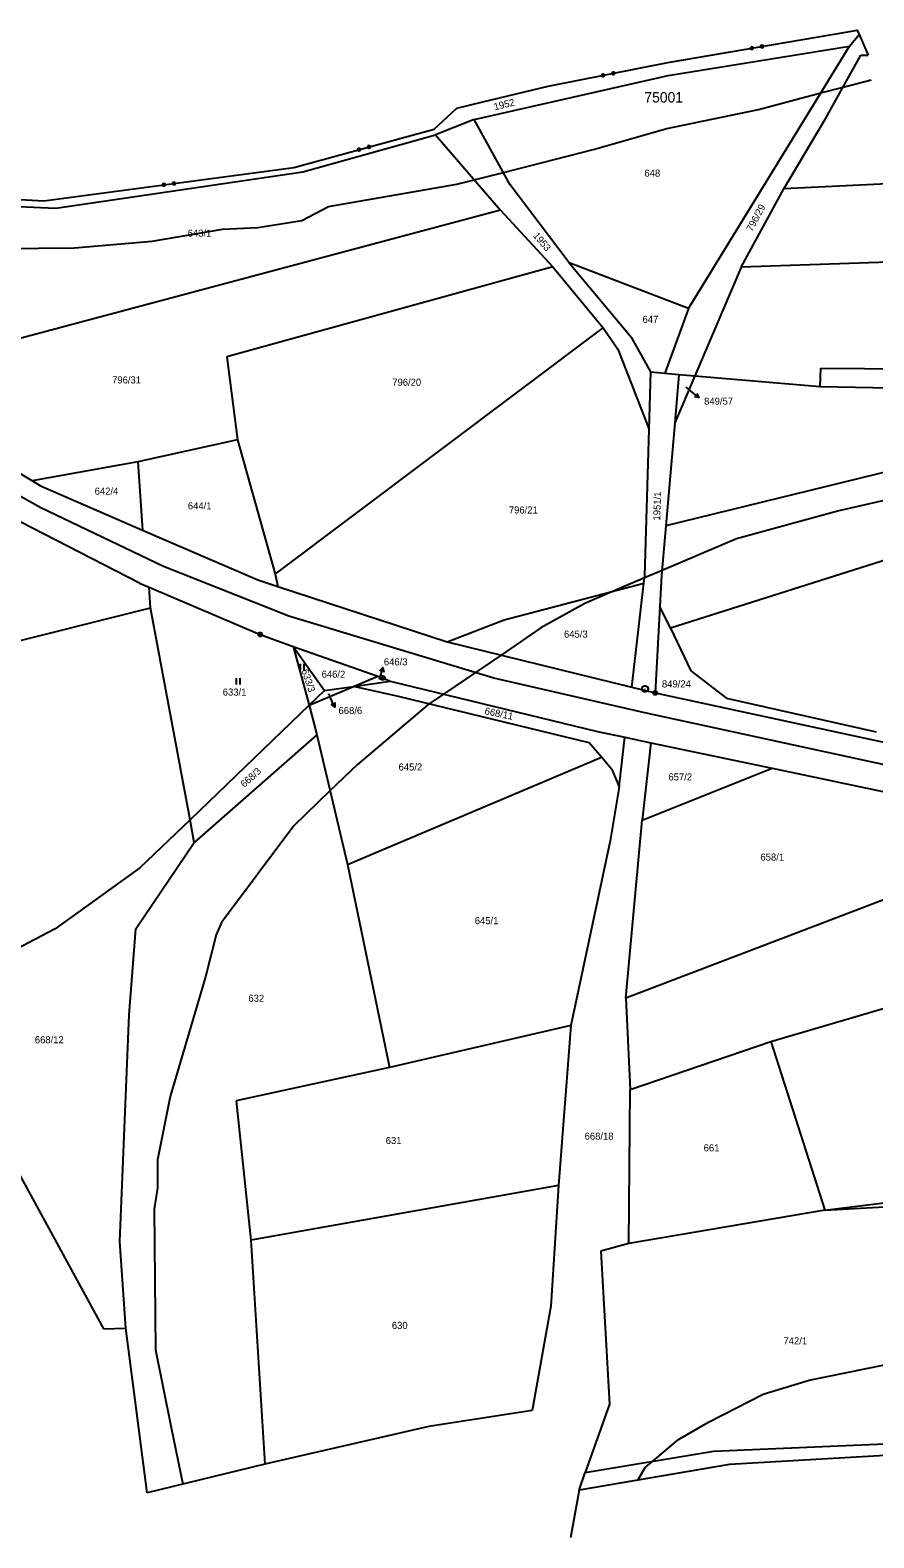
# Model space of a CAD drawing. Extents: x -789470 to -786707, y -1118640 to -1114455.
# Drawn here: x -789211.5 to -789008.6, y -1114817.3 to -1114454.9 of the extents above; entities that cross this region are included whole.
import ezdxf

# ---------------------------------------------------------------- set-up
doc = ezdxf.new("R2010")
doc.units = 0
for name, color, linetype in [('1', 7, 'Continuous'), ('11', 7, 'Continuous'), ('2', 7, 'Continuous'), ('3', 7, 'Continuous'), ('6', 7, 'Continuous'), ('7', 7, 'Continuous'), ('8', 7, 'Continuous')]:
    doc.layers.add(name, color=color, linetype=linetype)

msp = doc.modelspace()

# ---------------------------------------------------------------- linework, layer by layer
at = {"layer": '1'}
for p, q in [((-789058.11, -1114462.67), (-789015.34, -1114455.34)), ((-789015.34, -1114455.34), (-789012.6, -1114454.87)), ((-789014.4, -1114458.72), (-789012.14, -1114455.9)), ((-789012.6, -1114454.87), (-789012.14, -1114455.9)), ((-789012.14, -1114455.9), (-789009.91, -1114460.91)), ((-789058.02, -1114465.78), (-789014.4, -1114458.72)), ((-789053.12, -1114521.81), (-789014.4, -1114458.72)), ((-789020.14, -1114476.06), (-789011.74, -1114460.92)), ((-789011.74, -1114460.92), (-789009.91, -1114460.91)), ((-789086.93, -1114468.3), (-789058.11, -1114462.67)), ((-789104.7, -1114476.36), (-789058.02, -1114465.78)), ((-789102.63, -1114472.12), (-789086.93, -1114468.3)), ((-789108.83, -1114473.62), (-789102.63, -1114472.12)), ((-789114.34, -1114478.64), (-789108.83, -1114473.62)), ((-789030.25, -1114493.04), (-789020.14, -1114476.06)), ((-789148.09, -1114487.9), (-789114.34, -1114478.64)), ((-789104.7, -1114476.36), (-789114.01, -1114480.01)), ((-789096.01, -1114492.03), (-789104.7, -1114476.36)), ((-789145.89, -1114488.93), (-789114.01, -1114480.01)), ((-789114.01, -1114480.01), (-789098.37, -1114498.11)), ((-789208.22, -1114495.86), (-789148.09, -1114487.9)), ((-789205.27, -1114497.63), (-789145.89, -1114488.93)), ((-789081.84, -1114510.76), (-789096.01, -1114492.03)), ((-789040.51, -1114511.82), (-789030.25, -1114493.04)), ((-788982.26, -1114490.73), (-789030.25, -1114493.04)), ((-789235.33, -1114496.28), (-789205.27, -1114497.63)), ((-789233.65, -1114494.43), (-789208.22, -1114495.86)), ((-789098.37, -1114498.11), (-789235.7, -1114534.82)), ((-789098.37, -1114498.11), (-789085.8, -1114511.75)), ((-789085.8, -1114511.75), (-789164.15, -1114533.39)), ((-789085.8, -1114511.75), (-789073.65, -1114526.45)), ((-789081.84, -1114510.76), (-789066.76, -1114528.8)), ((-789053.12, -1114521.81), (-789081.84, -1114510.76)), ((-789040.51, -1114511.82), (-789051.65, -1114537.98)), ((-788977.92, -1114509.77), (-789040.51, -1114511.82)), ((-789053.12, -1114521.81), (-789058.81, -1114537.34)), ((-789152.59, -1114585.65), (-789073.65, -1114526.45)), ((-789073.65, -1114526.45), (-789070.17, -1114531.53)), ((-789062.23, -1114537.02), (-789066.76, -1114528.8)), ((-789164.15, -1114533.39), (-789161.58, -1114553.31)), ((-789070.17, -1114531.53), (-789062.63, -1114550.87)), ((-789062.63, -1114550.87), (-789062.23, -1114537.02)), ((-789062.23, -1114537.02), (-789058.81, -1114537.34)), ((-789058.81, -1114537.34), (-789055.45, -1114537.66)), ((-789055.45, -1114537.66), (-789056.45, -1114549.25)), ((-789055.45, -1114537.66), (-789051.65, -1114537.98)), ((-789021.49, -1114540.49), (-789021.34, -1114536.08)), ((-789021.34, -1114536.08), (-788942, -1114536.9)), ((-789051.65, -1114537.98), (-789056.45, -1114549.25)), ((-789051.65, -1114537.98), (-789021.49, -1114540.49)), ((-789021.49, -1114540.49), (-788941.63, -1114542.1)), ((-789211.01, -1114563.21), (-789234.48, -1114549.02)), ((-789063.65, -1114585.99), (-789062.63, -1114550.87)), ((-789056.45, -1114549.25), (-789058.59, -1114574)), ((-789161.58, -1114553.31), (-789185.62, -1114558.65)), ((-789161.58, -1114553.31), (-789152.59, -1114585.65)), ((-788973.71, -1114553.25), (-789058.59, -1114574)), ((-789185.62, -1114558.65), (-789211.01, -1114563.21)), ((-789185.62, -1114558.65), (-789184.43, -1114575.03)), ((-789185.19, -1114587.78), (-789226.93, -1114566.34)), ((-789209.16, -1114564.33), (-789211.01, -1114563.21)), ((-789209.16, -1114564.33), (-789184.43, -1114575.03)), ((-788978.27, -1114573.47), (-789057.48, -1114598.57)), ((-789184.43, -1114575.03), (-789156.73, -1114587.01)), ((-789058.59, -1114574), (-789059.61, -1114585.85)), ((-789185.19, -1114587.78), (-789182.88, -1114588.76)), ((-789156.73, -1114587.01), (-789151.91, -1114588.58)), ((-789152.59, -1114585.65), (-789151.91, -1114588.58)), ((-789097.51, -1114596.62), (-789063.86, -1114587.76)), ((-789066.78, -1114612.81), (-789063.86, -1114587.76)), ((-789063.86, -1114587.76), (-789063.65, -1114585.99)), ((-789059.61, -1114585.85), (-789060.02, -1114593.38)), ((-789182.53, -1114593.72), (-789182.88, -1114588.76)), ((-789182.88, -1114588.76), (-789156.19, -1114600.12)), ((-789151.91, -1114588.58), (-789111.21, -1114601.86)), ((-789254.23, -1114611.62), (-789182.53, -1114593.72)), ((-789173.03, -1114644.64), (-789182.53, -1114593.72)), ((-789060.02, -1114593.38), (-789061.16, -1114614.19)), ((-789057.48, -1114598.57), (-789060.02, -1114593.38)), ((-789111.21, -1114601.86), (-789097.51, -1114596.62)), ((-789057.48, -1114598.57), (-789052.56, -1114608.9)), ((-789156.19, -1114600.12), (-789148.2, -1114602.99)), ((-789111.21, -1114601.86), (-789066.78, -1114612.81)), ((-789148.2, -1114602.99), (-789140.73, -1114613.63)), ((-789148.2, -1114602.99), (-789144.37, -1114617.13)), ((-789148.2, -1114602.99), (-789127.89, -1114610.16)), ((-789133.75, -1114612.63), (-789127.89, -1114610.16)), ((-789127.89, -1114610.16), (-789126.69, -1114610.58)), ((-789052.56, -1114608.9), (-789043.9, -1114615.51)), ((-789144.37, -1114617.13), (-789133.75, -1114612.63)), ((-789140.73, -1114613.63), (-789144.37, -1114617.13)), ((-789140.73, -1114613.63), (-789133.75, -1114612.63)), ((-789133.75, -1114612.63), (-789124.89, -1114611.37)), ((-789122.87, -1114615.05), (-789133.75, -1114612.63)), ((-789126.69, -1114610.58), (-789124.89, -1114611.37)), ((-789124.89, -1114611.37), (-789075.07, -1114623.43)), ((-789066.78, -1114612.81), (-789061.16, -1114614.19)), ((-789144.37, -1114617.13), (-789173.03, -1114644.64)), ((-789144.37, -1114617.13), (-789142.56, -1114624.27)), ((-789077.02, -1114626.15), (-789122.87, -1114615.05)), ((-789061.16, -1114614.19), (-789002.52, -1114626.82)), ((-789007.92, -1114623.62), (-789043.9, -1114615.51)), ((-789142.56, -1114624.27), (-789172.01, -1114650.12)), ((-789142.56, -1114624.27), (-789135.19, -1114655.38)), ((-789075.07, -1114623.43), (-789068.5, -1114624.81)), ((-789074.08, -1114629.62), (-789077.02, -1114626.15)), ((-789069.8, -1114636.75), (-789068.5, -1114624.81)), ((-789068.5, -1114624.81), (-789062.17, -1114626.14)), ((-789062.17, -1114626.14), (-789064.29, -1114644.75)), ((-789062.17, -1114626.14), (-789033.04, -1114632.27)), ((-789135.19, -1114655.38), (-789074.08, -1114629.62)), ((-789071.61, -1114632.54), (-789074.08, -1114629.62)), ((-789071.61, -1114632.54), (-789069.8, -1114636.75)), ((-789064.29, -1114644.75), (-789033.04, -1114632.27)), ((-789033.04, -1114632.27), (-788962.34, -1114647.14)), ((-789069.8, -1114636.75), (-789072.01, -1114649.72)), ((-789173.03, -1114644.64), (-789185.07, -1114656.2)), ((-789172.01, -1114650.12), (-789173.03, -1114644.64)), ((-789068.19, -1114687.52), (-789064.29, -1114644.75)), ((-789072.01, -1114649.72), (-789081.42, -1114694.09)), ((-788962.34, -1114647.14), (-789068.19, -1114687.52)), ((-789186.06, -1114670.85), (-789172.01, -1114650.12)), ((-789185.07, -1114656.2), (-789205.44, -1114670.9)), ((-789135.19, -1114655.38), (-789125.09, -1114704.18)), ((-789205.44, -1114670.9), (-789224.81, -1114680.95)), ((-789187.7, -1114691.53), (-789186.06, -1114670.85)), ((-789033.32, -1114697.94), (-788966.91, -1114678.44)), ((-789068.19, -1114687.52), (-789067.21, -1114709.5)), ((-789189.88, -1114746), (-789187.7, -1114691.53)), ((-789081.42, -1114694.09), (-789125.09, -1114704.18)), ((-789081.42, -1114694.09), (-789084.4, -1114732.6)), ((-789067.21, -1114709.5), (-789033.32, -1114697.94)), ((-789033.32, -1114697.94), (-789020.4, -1114738.52)), ((-789229.14, -1114702.4), (-789193.8, -1114767.06)), ((-789125.09, -1114704.18), (-789161.91, -1114712.24)), ((-789067.47, -1114746.51), (-789067.21, -1114709.5)), ((-789161.91, -1114712.24), (-789158.44, -1114745.74)), ((-789084.4, -1114732.6), (-789158.44, -1114745.74)), ((-789084.4, -1114732.6), (-789086.25, -1114761.61)), ((-789020.4, -1114738.52), (-788983.29, -1114733.88)), ((-789020.4, -1114738.52), (-788982.99, -1114736.42)), ((-789020.4, -1114738.52), (-789067.47, -1114746.51)), ((-789188.44, -1114766.9), (-789189.88, -1114746)), ((-789158.44, -1114745.74), (-789155.02, -1114799.55)), ((-789067.47, -1114746.51), (-789074.21, -1114748.39)), ((-789074.21, -1114748.39), (-789072.14, -1114785.12)), ((-789086.25, -1114761.61), (-789090.77, -1114786.68)), ((-789193.8, -1114767.06), (-789188.44, -1114766.9)), ((-789183.37, -1114806.46), (-789188.44, -1114766.9)), ((-789090.77, -1114786.68), (-789115.62, -1114790.46)), ((-789072.14, -1114785.12), (-789078.02, -1114801.56)), ((-789115.62, -1114790.46), (-789155.02, -1114799.55)), ((-789047.11, -1114796.42), (-788981.24, -1114793.65)), ((-789078.02, -1114801.56), (-789047.11, -1114796.42)), ((-788986.34, -1114796.35), (-789043.29, -1114799.67)), ((-789155.02, -1114799.55), (-789183.37, -1114806.46)), ((-789043.29, -1114799.67), (-789079.41, -1114805.81)), ((-789079.41, -1114805.81), (-789078.02, -1114801.56)), ((-789079.41, -1114805.81), (-789081.5, -1114817.26))]:
    msp.add_line(p, q, dxfattribs=at)
for points in [[(-789037.83, -1114458.87), (-789037.61, -1114459.03), (-789037.57, -1114459.29), (-789037.72, -1114459.51), (-789037.99, -1114459.56), (-789038.21, -1114459.4), (-789038.25, -1114459.14), (-789038.1, -1114458.92), (-789037.83, -1114458.87), (-789037.84, -1114458.91), (-789038.07, -1114458.95), (-789038.14, -1114459.04), (-789037.74, -1114458.98), (-789037.65, -1114459.04), (-789038.2, -1114459.14), (-789038.19, -1114459.22), (-789037.64, -1114459.12), (-789037.62, -1114459.2), (-789038.18, -1114459.29), (-789038.16, -1114459.37), (-789037.61, -1114459.28), (-789037.68, -1114459.37), (-789038.07, -1114459.44), (-789037.98, -1114459.5), (-789037.74, -1114459.46)], [(-789035.37, -1114458.45), (-789035.15, -1114458.6), (-789035.1, -1114458.87), (-789035.26, -1114459.09), (-789035.53, -1114459.13), (-789035.75, -1114458.98), (-789035.79, -1114458.71), (-789035.64, -1114458.49), (-789035.37, -1114458.45), (-789035.39, -1114458.49), (-789035.63, -1114458.53), (-789035.69, -1114458.63), (-789035.3, -1114458.56), (-789035.21, -1114458.62), (-789035.76, -1114458.72), (-789035.75, -1114458.8), (-789035.19, -1114458.7), (-789035.18, -1114458.78), (-789035.73, -1114458.88), (-789035.72, -1114458.95), (-789035.17, -1114458.86), (-789035.23, -1114458.95), (-789035.63, -1114459.02), (-789035.53, -1114459.08), (-789035.3, -1114459.04)], [(-789071.18, -1114464.9), (-789070.96, -1114465.05), (-789070.9, -1114465.31), (-789071.05, -1114465.53), (-789071.32, -1114465.59), (-789071.54, -1114465.44), (-789071.59, -1114465.17), (-789071.44, -1114464.95), (-789071.18, -1114464.9), (-789071.2, -1114464.94), (-789071.44, -1114464.99), (-789071.5, -1114465.08), (-789071.11, -1114465), (-789071.01, -1114465.07), (-789071.56, -1114465.18), (-789071.55, -1114465.25), (-789071, -1114465.15), (-789070.98, -1114465.23), (-789071.53, -1114465.33), (-789071.52, -1114465.41), (-789070.97, -1114465.3), (-789071.03, -1114465.4), (-789071.42, -1114465.47), (-789071.33, -1114465.54), (-789071.09, -1114465.49)], [(-789073.63, -1114465.38), (-789073.41, -1114465.53), (-789073.36, -1114465.79), (-789073.51, -1114466.01), (-789073.77, -1114466.07), (-789073.99, -1114465.92), (-789074.05, -1114465.65), (-789073.9, -1114465.43), (-789073.63, -1114465.38), (-789073.63, -1114465.42), (-789073.87, -1114465.46), (-789073.93, -1114465.56), (-789073.54, -1114465.48), (-789073.45, -1114465.54), (-789074, -1114465.65), (-789073.98, -1114465.73), (-789073.43, -1114465.62), (-789073.42, -1114465.7), (-789073.96, -1114465.81), (-789073.95, -1114465.89), (-789073.4, -1114465.78), (-789073.46, -1114465.87), (-789073.86, -1114465.95), (-789073.76, -1114466.01), (-789073.53, -1114465.97)], [(-789132.33, -1114483.24), (-789132.1, -1114483.38), (-789132.03, -1114483.64), (-789132.16, -1114483.87), (-789132.42, -1114483.94), (-789132.65, -1114483.81), (-789132.72, -1114483.55), (-789132.59, -1114483.32), (-789132.33, -1114483.24), (-789132.33, -1114483.29), (-789132.56, -1114483.35), (-789132.62, -1114483.45), (-789132.23, -1114483.34), (-789132.13, -1114483.4), (-789132.67, -1114483.55), (-789132.65, -1114483.62), (-789132.11, -1114483.48), (-789132.09, -1114483.55), (-789132.63, -1114483.7), (-789132.61, -1114483.78), (-789132.07, -1114483.63), (-789132.13, -1114483.73), (-789132.51, -1114483.83), (-789132.41, -1114483.89), (-789132.18, -1114483.83)], [(-789129.92, -1114482.58), (-789129.69, -1114482.72), (-789129.62, -1114482.98), (-789129.75, -1114483.21), (-789130.01, -1114483.28), (-789130.24, -1114483.15), (-789130.31, -1114482.89), (-789130.18, -1114482.65), (-789129.92, -1114482.58), (-789129.94, -1114482.63), (-789130.17, -1114482.69), (-789130.23, -1114482.79), (-789129.84, -1114482.69), (-789129.74, -1114482.74), (-789130.28, -1114482.89), (-789130.26, -1114482.97), (-789129.72, -1114482.82), (-789129.7, -1114482.9), (-789130.24, -1114483.04), (-789130.22, -1114483.12), (-789129.68, -1114482.97), (-789129.73, -1114483.07), (-789130.12, -1114483.18), (-789130.02, -1114483.23), (-789129.79, -1114483.17)], [(-789179.26, -1114491.7), (-789179.04, -1114491.87), (-789179.01, -1114492.13), (-789179.17, -1114492.35), (-789179.44, -1114492.38), (-789179.65, -1114492.22), (-789179.69, -1114491.95), (-789179.53, -1114491.74), (-789179.26, -1114491.7), (-789179.26, -1114491.74), (-789179.5, -1114491.78), (-789179.57, -1114491.87), (-789179.17, -1114491.81), (-789179.08, -1114491.88), (-789179.64, -1114491.96), (-789179.63, -1114492.04), (-789179.07, -1114491.96), (-789179.06, -1114492.04), (-789179.62, -1114492.11), (-789179.61, -1114492.19), (-789179.05, -1114492.12), (-789179.12, -1114492.21), (-789179.52, -1114492.26), (-789179.43, -1114492.33), (-789179.19, -1114492.3)], [(-789176.78, -1114491.37), (-789176.57, -1114491.54), (-789176.53, -1114491.81), (-789176.69, -1114492.02), (-789176.96, -1114492.05), (-789177.18, -1114491.89), (-789177.21, -1114491.62), (-789177.05, -1114491.41), (-789176.78, -1114491.37), (-789176.8, -1114491.42), (-789177.04, -1114491.45), (-789177.11, -1114491.54), (-789176.71, -1114491.49), (-789176.62, -1114491.56), (-789177.18, -1114491.63), (-789177.17, -1114491.71), (-789176.61, -1114491.64), (-789176.6, -1114491.71), (-789177.16, -1114491.79), (-789177.15, -1114491.87), (-789176.59, -1114491.79), (-789176.66, -1114491.88), (-789177.06, -1114491.94), (-789176.97, -1114492), (-789176.73, -1114491.97)]]:
    msp.add_lwpolyline(points, dxfattribs=at)
at = {"layer": '11'}
for points in [[(-789309.5, -1114485.53), (-789305.22, -1114485.95), (-789297.1, -1114486.75), (-789298.04, -1114487.53), (-789284.18, -1114488.99), (-789233.65, -1114494.43), (-789208.22, -1114495.86), (-789148.09, -1114487.9), (-789114.34, -1114478.64), (-789108.83, -1114473.62), (-789102.63, -1114472.12), (-789086.93, -1114468.3), (-789058.11, -1114462.67), (-789015.34, -1114455.34), (-789012.6, -1114454.87), (-789012.14, -1114455.9), (-789009.91, -1114460.91)], [(-789306.68, -1114493.77), (-789304.24, -1114494.87), (-789293.55, -1114499.73), (-789275.34, -1114502.75), (-789238.07, -1114507.53), (-789235.44, -1114507.5), (-789200.79, -1114507.22), (-789182.14, -1114505.59), (-789165.19, -1114502.68), (-789156.72, -1114502.29), (-789146.12, -1114500.63), (-789139.76, -1114497.27), (-789108.83, -1114491.87), (-789104.67, -1114490.82), (-789097.67, -1114489.05), (-789075.77, -1114483.51), (-789058.39, -1114478.49), (-789036.35, -1114473.91), (-789021.31, -1114469.97), (-789015.99, -1114468.58), (-789009.22, -1114466.81)], [(-788986.09, -1114563.33), (-789017.03, -1114570.42), (-789041.61, -1114577.11), (-789059.51, -1114584.74), (-789063.71, -1114586.53), (-789071.06, -1114589.66), (-789078.07, -1114592.64), (-789088.67, -1114598.53), (-789098.24, -1114605.06), (-789112.05, -1114614.48), (-789115.5, -1114616.83), (-789115.82, -1114617.06), (-789132.79, -1114631.38), (-789139.37, -1114637.74), (-789148.06, -1114646.14), (-789165.47, -1114669.35), (-789166.75, -1114672.31), (-789169.31, -1114682.45), (-789177.83, -1114711.19), (-789180.82, -1114726.41), (-789180.83, -1114733.17), (-789181.69, -1114738.25), (-789181.32, -1114772.09), (-789177.54, -1114790.71), (-789174.77, -1114804.36), (-789174.77, -1114804.36)], [(-789065.35, -1114803.42), (-789063.59, -1114800.39), (-789061.76, -1114798.86), (-789055.53, -1114793.64), (-789048.32, -1114789.44), (-789035.18, -1114782.71), (-789024.16, -1114779.36), (-789001.7, -1114774.78)]]:
    msp.add_lwpolyline(points, dxfattribs=at)
at = {"layer": '3'}
for p, q in [((-789146.58, -1114607.18), (-789146.58, -1114608.68)), ((-789145.58, -1114608.68), (-789145.58, -1114607.18)), ((-789161.95, -1114610.64), (-789161.95, -1114612.14)), ((-789160.95, -1114612.14), (-789160.95, -1114610.64))]:
    msp.add_line(p, q, dxfattribs=at)
at = {"layer": '6'}
for p, q in [((-789208.89, -1114569.65), (-789234.69, -1114555.47)), ((-789179.37, -1114583.82), (-789208.89, -1114569.65)), ((-789149.25, -1114595.76), (-789179.37, -1114583.82)), ((-789099.94, -1114610.66), (-789149.25, -1114595.76)), ((-789063.67, -1114618.94), (-789099.94, -1114610.66)), ((-789004.18, -1114631.89), (-789063.67, -1114618.94))]:
    msp.add_line(p, q, dxfattribs=at)
at = {"layer": '7'}
for p, q in [((-789053.8, -1114540.72), (-789052.99, -1114541.35)), ((-789050.63, -1114543.2), (-789052.99, -1114541.35)), ((-789126.63, -1114608.1), (-789127.56, -1114610.95)), ((-789127.57, -1114610.97), (-789127.56, -1114610.95)), ((-789139.72, -1114614.4), (-789139.5, -1114614.85)), ((-789138.21, -1114617.56), (-789139.5, -1114614.85))]:
    msp.add_line(p, q, dxfattribs=at)
for points in [[(-789051.11, -1114542.19), (-789050.63, -1114543.2), (-789051.72, -1114542.98)], [(-789127.41, -1114608.89), (-789126.63, -1114608.1), (-789126.46, -1114609.2)], [(-789138.19, -1114616.44), (-789138.21, -1114617.56), (-789139.09, -1114616.87)]]:
    msp.add_lwpolyline(points, dxfattribs=at)
at = {"layer": '8'}
for p, q in [((-789156.31, -1114600.12), (-789156.07, -1114600.12)), ((-789126.81, -1114610.58), (-789126.57, -1114610.58)), ((-789063.65, -1114613.19), (-789063.55, -1114613.19)), ((-789061.28, -1114614.19), (-789061.04, -1114614.19))]:
    msp.add_line(p, q, dxfattribs=at)
for points in [[(-789156.04, -1114599.64), (-789155.79, -1114599.82), (-789155.69, -1114600.11), (-789155.79, -1114600.4), (-789156.04, -1114600.58), (-789156.35, -1114600.58), (-789156.6, -1114600.4), (-789156.7, -1114600.11), (-789156.6, -1114599.82), (-789156.35, -1114599.64)], [(-789126.54, -1114610.1), (-789126.29, -1114610.28), (-789126.19, -1114610.57), (-789126.29, -1114610.86), (-789126.54, -1114611.04), (-789126.85, -1114611.04), (-789127.1, -1114610.86), (-789127.2, -1114610.57), (-789127.1, -1114610.28), (-789126.85, -1114610.1)], [(-789063.41, -1114612.47), (-789063.07, -1114612.66), (-789062.88, -1114613), (-789062.88, -1114613.39), (-789063.07, -1114613.73), (-789063.41, -1114613.92), (-789063.8, -1114613.92), (-789064.14, -1114613.73), (-789064.33, -1114613.39), (-789064.33, -1114613), (-789064.14, -1114612.66), (-789063.8, -1114612.47)], [(-789061.01, -1114613.71), (-789060.76, -1114613.89), (-789060.66, -1114614.18), (-789060.76, -1114614.47), (-789061.01, -1114614.65), (-789061.32, -1114614.65), (-789061.57, -1114614.47), (-789061.67, -1114614.18), (-789061.57, -1114613.89), (-789061.32, -1114613.71)]]:
    msp.add_lwpolyline(points, close=True, dxfattribs=at)

# ---------------------------------------------------------------- texts
at = {"layer": '11'}
msp.add_text('75001', height=2.5, dxfattribs=at).set_placement((-789063.76, -1114472.26))
at = {"layer": '2'}
for s, rotation, p in [('1952', 13.5791, (-789099.74, -1114474.16)), ('796/29', 61.7076, (-789037.86, -1114503.42)), ('1953', 310.2566, (-789090.65, -1114504.32)), ('1951/1', 87.8917, (-789059.97, -1114572.76)), ('633/3', 288.6561, (-789146.28, -1114608.77)), ('668/11', 348.5302, (-789102.3, -1114619.28)), ('668/3', 42.3989, (-789159.95, -1114637.03))]:
    msp.add_text(s, height=1.7, rotation=rotation, dxfattribs=at).set_placement(p)
for s, height, p in [('648', 1.7, (-789063.75, -1114490.08)), ('643/1', 1.7, (-789173.59, -1114504.51)), ('647', 1.7, (-789064.2, -1114525.23)), ('796/31', 1.7, (-789191.77, -1114539.79)), ('796/20', 1.7, (-789124.4, -1114540.35)), ('849/57', 0.1, (-789054.04, -1114540.72)), ('642/4', 1.7, (-789195.97, -1114566.52)), ('644/1', 1.7, (-789173.55, -1114570.05)), ('796/21', 1.7, (-789096.35, -1114571.05)), ('645/3', 1.7, (-789083.09, -1114600.89)), ('646/2', 1.7, (-789141.38, -1114610.52)), ('633/1', 1.7, (-789165.16, -1114614.82)), ('646/3', 0.1, (-789127.78, -1114610.97)), ('849/24', 1.7, (-789059.54, -1114612.86)), ('668/6', 0.1, (-789139.92, -1114614.4)), ('645/2', 1.7, (-789122.88, -1114632.82)), ('657/2', 1.7, (-789057.98, -1114635.22)), ('658/1', 1.7, (-789035.85, -1114654.48)), ('645/1', 1.7, (-789104.55, -1114669.76)), ('632', 1.7, (-789158.99, -1114688.41)), ('668/12', 1.7, (-789210.35, -1114698.38)), ('631', 1.7, (-789125.96, -1114722.6)), ('668/18', 1.7, (-789078.13, -1114721.56)), ('661', 1.7, (-789049.51, -1114724.37)), ('630', 1.7, (-789124.49, -1114767.04)), ('742/1', 1.7, (-789030.32, -1114770.76))]:
    msp.add_text(s, height=height, dxfattribs=at).set_placement(p)
at = {"layer": '7'}
for s, p in [('849/57', (-789049.39, -1114544.9)), ('646/3', (-789126.41, -1114607.54)), ('668/6', (-789137.32, -1114619.26))]:
    msp.add_text(s, height=1.7, dxfattribs=at).set_placement(p)

doc.saveas('drawing.dxf')
